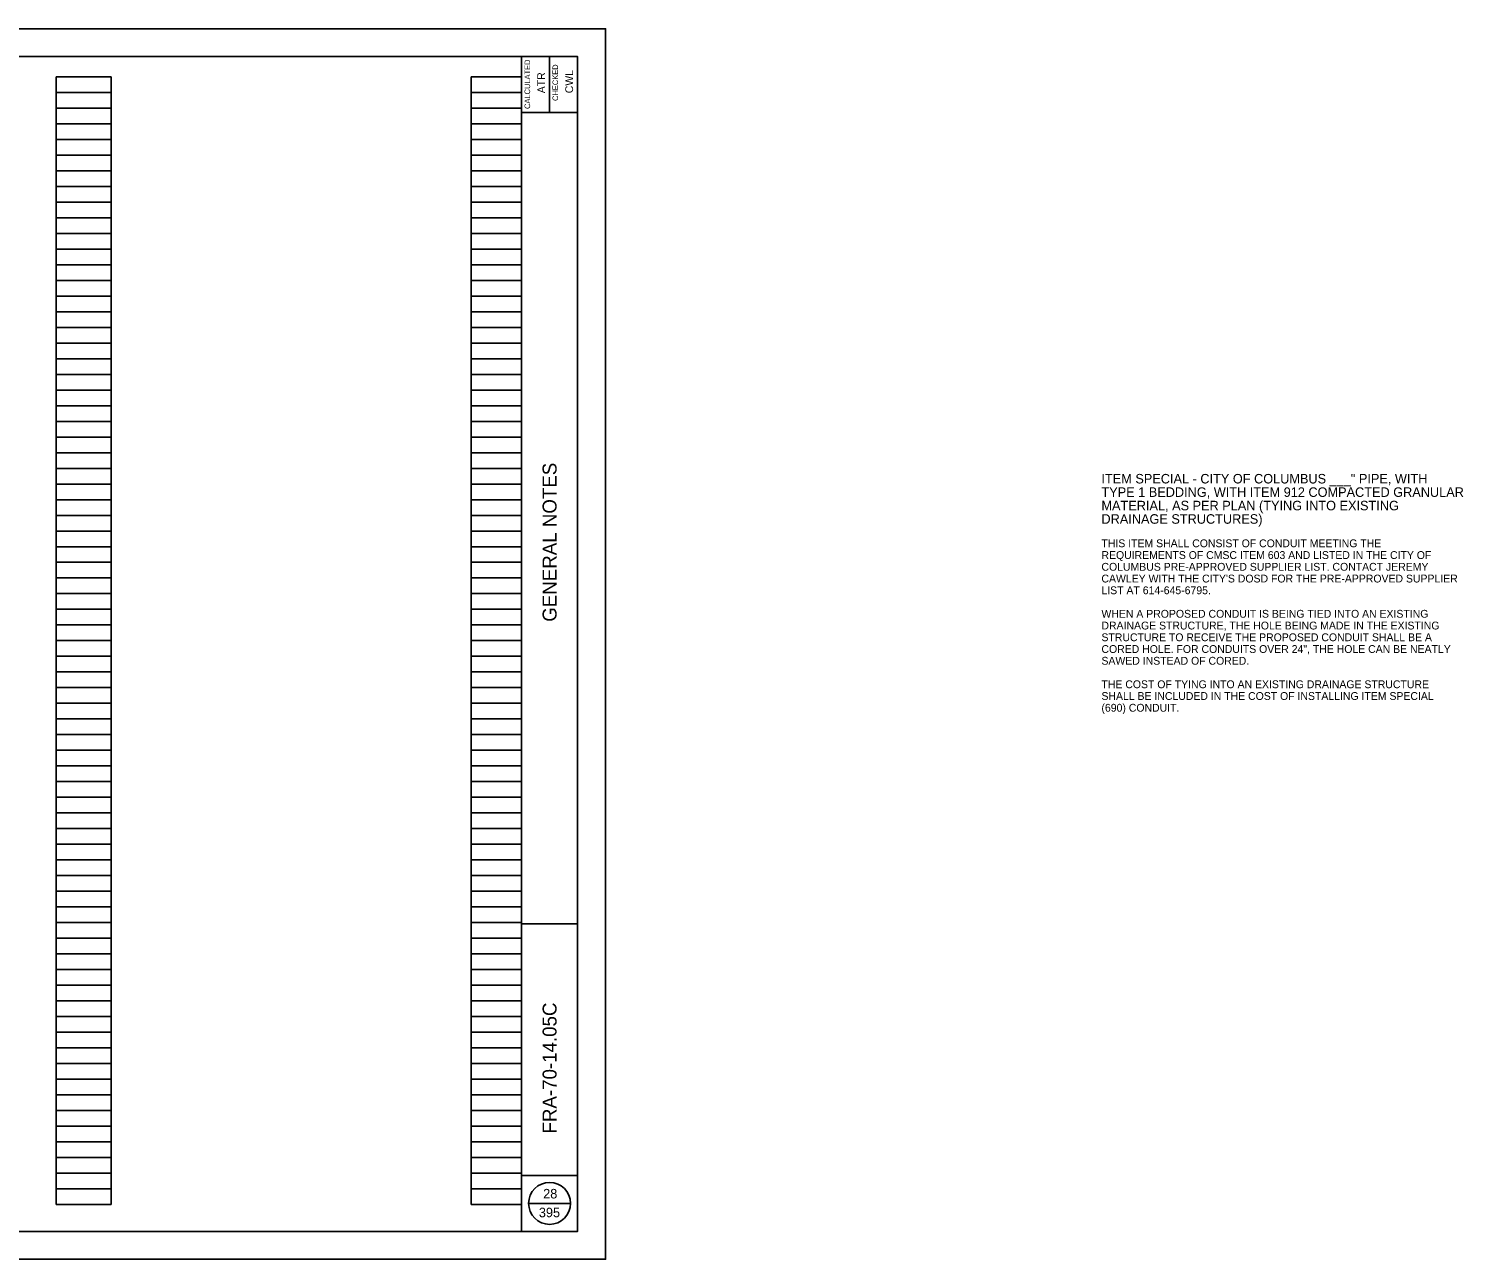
# Model space of a CAD drawing. Extents: x 0 to 49.3, y 0 to 22.
# Drawn here: x 23.69 to 49.34, y 0 to 22 of the extents above; entities that cross this region are included whole.
import ezdxf

# ---------------------------------------------------------------- set-up
doc = ezdxf.new("R2010")
doc.units = 0
for name, color, linetype in [('SC_Scratch1', 7, 'Continuous'), ('SH_Border', 7, 'Continuous'), ('SH_Cut_Line', 7, 'Continuous'), ('SH_Data', 7, 'Continuous'), ('SH_Text', 7, 'Continuous'), ('TX_P_Misc', 7, 'Continuous')]:
    doc.layers.add(name, color=color, linetype=linetype)

msp = doc.modelspace()

# ---------------------------------------------------------------- linework, layer by layer
at = {"layer": 'SC_Scratch1'}
for p, q in [((24.18, 0.98), (24.18, 21.14)), ((24.18, 21.14), (25.16, 21.14)), ((25.16, 0.98), (25.16, 21.14)), ((31.6, 0.98), (31.6, 21.14)), ((31.6, 21.14), (32.5, 21.14)), ((32.5, 0.98), (32.5, 21.14)), ((24.18, 20.86), (25.16, 20.86)), ((31.6, 20.86), (32.5, 20.86)), ((24.18, 20.58), (25.16, 20.58)), ((31.6, 20.58), (32.5, 20.58)), ((24.18, 20.3), (25.16, 20.3)), ((31.6, 20.3), (32.5, 20.3)), ((24.18, 20.02), (25.16, 20.02)), ((31.6, 20.02), (32.5, 20.02)), ((24.18, 19.74), (25.16, 19.74)), ((31.6, 19.74), (32.5, 19.74)), ((24.18, 19.46), (25.16, 19.46)), ((31.6, 19.46), (32.5, 19.46)), ((24.18, 19.18), (25.16, 19.18)), ((31.6, 19.18), (32.5, 19.18)), ((24.18, 18.9), (25.16, 18.9)), ((31.6, 18.9), (32.5, 18.9)), ((24.18, 18.62), (25.16, 18.62)), ((31.6, 18.62), (32.5, 18.62)), ((24.18, 18.34), (25.16, 18.34)), ((31.6, 18.34), (32.5, 18.34)), ((24.18, 18.06), (25.16, 18.06)), ((31.6, 18.06), (32.5, 18.06)), ((24.18, 17.78), (25.16, 17.78)), ((31.6, 17.78), (32.5, 17.78)), ((24.18, 17.5), (25.16, 17.5)), ((31.6, 17.5), (32.5, 17.5)), ((24.18, 17.22), (25.16, 17.22)), ((31.6, 17.22), (32.5, 17.22)), ((24.18, 16.94), (25.16, 16.94)), ((31.6, 16.94), (32.5, 16.94)), ((24.18, 16.66), (25.16, 16.66)), ((31.6, 16.66), (32.5, 16.66)), ((24.18, 16.38), (25.16, 16.38)), ((31.6, 16.38), (32.5, 16.38)), ((24.18, 16.1), (25.16, 16.1)), ((31.6, 16.1), (32.5, 16.1)), ((24.18, 15.82), (25.16, 15.82)), ((31.6, 15.82), (32.5, 15.82)), ((24.18, 15.54), (25.16, 15.54)), ((31.6, 15.54), (32.5, 15.54)), ((24.18, 15.26), (25.16, 15.26)), ((31.6, 15.26), (32.5, 15.26)), ((24.18, 14.98), (25.16, 14.98)), ((31.6, 14.98), (32.5, 14.98)), ((24.18, 14.7), (25.16, 14.7)), ((31.6, 14.7), (32.5, 14.7)), ((24.18, 14.42), (25.16, 14.42)), ((31.6, 14.42), (32.5, 14.42)), ((24.18, 14.14), (25.16, 14.14)), ((31.6, 14.14), (32.5, 14.14)), ((24.18, 13.86), (25.16, 13.86)), ((31.6, 13.86), (32.5, 13.86)), ((24.18, 13.58), (25.16, 13.58)), ((31.6, 13.58), (32.5, 13.58)), ((24.18, 13.3), (25.16, 13.3)), ((31.6, 13.3), (32.5, 13.3)), ((24.18, 13.02), (25.16, 13.02)), ((31.6, 13.02), (32.5, 13.02)), ((24.18, 12.74), (25.16, 12.74)), ((31.6, 12.74), (32.5, 12.74)), ((24.18, 12.46), (25.16, 12.46)), ((31.6, 12.46), (32.5, 12.46)), ((24.18, 12.18), (25.16, 12.18)), ((31.6, 12.18), (32.5, 12.18)), ((24.18, 11.9), (25.16, 11.9)), ((31.6, 11.9), (32.5, 11.9)), ((24.18, 11.62), (25.16, 11.62)), ((31.6, 11.62), (32.5, 11.62)), ((24.18, 11.34), (25.16, 11.34)), ((31.6, 11.34), (32.5, 11.34)), ((24.18, 11.06), (25.16, 11.06)), ((31.6, 11.06), (32.5, 11.06)), ((24.18, 10.78), (25.16, 10.78)), ((31.6, 10.78), (32.5, 10.78)), ((24.18, 10.5), (25.16, 10.5)), ((31.6, 10.5), (32.5, 10.5)), ((24.18, 10.22), (25.16, 10.22)), ((31.6, 10.22), (32.5, 10.22)), ((24.18, 9.94), (25.16, 9.94)), ((31.6, 9.94), (32.5, 9.94)), ((24.18, 9.66), (25.16, 9.66)), ((31.6, 9.66), (32.5, 9.66)), ((24.18, 9.38), (25.16, 9.38)), ((31.6, 9.38), (32.5, 9.38)), ((24.18, 9.1), (25.16, 9.1)), ((31.6, 9.1), (32.5, 9.1)), ((24.18, 8.82), (25.16, 8.82)), ((31.6, 8.82), (32.5, 8.82)), ((24.18, 8.54), (25.16, 8.54)), ((31.6, 8.54), (32.5, 8.54)), ((24.18, 8.26), (25.16, 8.26)), ((31.6, 8.26), (32.5, 8.26)), ((24.18, 7.98), (25.16, 7.98)), ((31.6, 7.98), (32.5, 7.98)), ((24.18, 7.7), (25.16, 7.7)), ((31.6, 7.7), (32.5, 7.7)), ((24.18, 7.42), (25.16, 7.42)), ((31.6, 7.42), (32.5, 7.42)), ((24.18, 7.14), (25.16, 7.14)), ((31.6, 7.14), (32.5, 7.14)), ((24.18, 6.86), (25.16, 6.86)), ((31.6, 6.86), (32.5, 6.86)), ((24.18, 6.58), (25.16, 6.58)), ((31.6, 6.58), (32.5, 6.58)), ((24.18, 6.3), (25.16, 6.3)), ((31.6, 6.3), (32.5, 6.3)), ((24.18, 6.02), (25.16, 6.02)), ((31.6, 6.02), (32.5, 6.02)), ((24.18, 5.74), (25.16, 5.74)), ((31.6, 5.74), (32.5, 5.74)), ((24.18, 5.46), (25.16, 5.46)), ((31.6, 5.46), (32.5, 5.46)), ((24.18, 5.18), (25.16, 5.18)), ((31.6, 5.18), (32.5, 5.18)), ((24.18, 4.9), (25.16, 4.9)), ((31.6, 4.9), (32.5, 4.9)), ((24.18, 4.62), (25.16, 4.62)), ((31.6, 4.62), (32.5, 4.62)), ((24.18, 4.34), (25.16, 4.34)), ((31.6, 4.34), (32.5, 4.34)), ((24.18, 4.06), (25.16, 4.06)), ((31.6, 4.06), (32.5, 4.06)), ((24.18, 3.78), (25.16, 3.78)), ((31.6, 3.78), (32.5, 3.78)), ((24.18, 3.5), (25.16, 3.5)), ((31.6, 3.5), (32.5, 3.5)), ((24.18, 3.22), (25.16, 3.22)), ((31.6, 3.22), (32.5, 3.22)), ((24.18, 2.94), (25.16, 2.94)), ((31.6, 2.94), (32.5, 2.94)), ((24.18, 2.66), (25.16, 2.66)), ((31.6, 2.66), (32.5, 2.66)), ((24.18, 2.38), (25.16, 2.38)), ((31.6, 2.38), (32.5, 2.38)), ((24.18, 2.1), (25.16, 2.1)), ((31.6, 2.1), (32.5, 2.1)), ((24.18, 1.82), (25.16, 1.82)), ((31.6, 1.82), (32.5, 1.82)), ((24.18, 1.54), (25.16, 1.54)), ((31.6, 1.54), (32.5, 1.54)), ((24.18, 1.26), (25.16, 1.26)), ((31.6, 1.26), (32.5, 1.26)), ((24.18, 0.98), (25.16, 0.98)), ((31.6, 0.98), (32.5, 0.98))]:
    msp.add_line(p, q, dxfattribs=at)
at = {"layer": 'SH_Border'}
for p, q in [((32.5, 0.5), (32.5, 21.5)), ((33, 21.5), (33, 20.5)), ((32.5, 20.5), (33.5, 20.5)), ((32.5, 6), (33.5, 6)), ((32.5, 1.5), (33.5, 1.5))]:
    msp.add_line(p, q, dxfattribs=at)
msp.add_lwpolyline([(2, 21.5), (33.5, 21.5), (33.5, 0.5), (2, 0.5)], close=True, dxfattribs=at)
at = {"layer": 'SH_Cut_Line'}
msp.add_lwpolyline([(0, 0), (34, 0), (34, 22), (0, 22)], close=True, dxfattribs=at)
at = {"layer": 'SH_Data'}
msp.add_line((32.625, 1), (33.375, 1), dxfattribs=at)
msp.add_circle((33, 1), 0.375, dxfattribs=at)

# ---------------------------------------------------------------- texts
for s, height, p in [('CALCULATED', 0.1, (32.652, 20.565)), ('CHECKED', 0.1, (33.152, 20.708)), ('ATR', 0.14, (32.92, 20.846)), ('CWL', 0.14, (33.42, 20.846)), ('GENERAL NOTES', 0.25, (33.125, 11.398)), ('FRA-70-14.05C', 0.25, (33.125, 2.249))]:
    msp.add_text(s, height=height, rotation=90, dxfattribs=at).set_placement(p)
for s, p in [('28', (32.885, 1.088)), ('395', (32.808, 0.752))]:
    msp.add_text(s, height=0.17, dxfattribs=at).set_placement(p)
at = {"layer": 'SH_Text'}
for s, p in [('THIS ITEM SHALL CONSIST OF CONDUIT MEETING THE ', (42.867, 12.73)), ('REQUIREMENTS OF CMSC ITEM 603 AND LISTED IN THE CITY OF ', (42.867, 12.52)), ('COLUMBUS PRE-APPROVED SUPPLIER LIST. CONTACT JEREMY ', (42.867, 12.31)), ("CAWLEY WITH THE CITY'S DOSD FOR THE PRE-APPROVED SUPPLIER ", (42.867, 12.1)), ('LIST AT 614-645-6795.', (42.867, 11.89)), ('WHEN A PROPOSED CONDUIT IS BEING TIED INTO AN EXISTING ', (42.867, 11.47)), ('DRAINAGE STRUCTURE, THE HOLE BEING MADE IN THE EXISTING ', (42.867, 11.26)), ('STRUCTURE TO RECEIVE THE PROPOSED CONDUIT SHALL BE A ', (42.867, 11.05)), ('CORED HOLE. FOR CONDUITS OVER 24", THE HOLE CAN BE NEATLY ', (42.867, 10.84)), ('SAWED INSTEAD OF CORED.', (42.867, 10.63)), ('THE COST OF TYING INTO AN EXISTING DRAINAGE STRUCTURE ', (42.867, 10.21)), ('SHALL BE INCLUDED IN THE COST OF INSTALLING ITEM SPECIAL ', (42.867, 10)), ('(690) CONDUIT.', (42.867, 9.79))]:
    msp.add_text(s, height=0.14, dxfattribs=at).set_placement(p)
at = {"layer": 'TX_P_Misc'}
for s, p in [('ITEM SPECIAL - CITY OF COLUMBUS ___" PIPE, WITH ', (42.867, 13.87)), ('TYPE 1 BEDDING, WITH ITEM 912 COMPACTED GRANULAR ', (42.867, 13.63)), ('MATERIAL, AS PER PLAN (TYING INTO EXISTING ', (42.867, 13.39)), ('DRAINAGE STRUCTURES)', (42.867, 13.15))]:
    msp.add_text(s, height=0.17, dxfattribs=at).set_placement(p)

doc.saveas('drawing.dxf')
